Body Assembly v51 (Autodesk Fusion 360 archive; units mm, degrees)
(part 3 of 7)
circular_pattern "C-Pattern1" TotalAngle 360
align "Align1"
circular_pattern "C-Pattern1" TotalAngle 360
circular_pattern "C-Pattern2" TotalAngle 360
copy_paste_bodies "CopyPasteBodies1"
move "Move4"
align "Align7"
offset_faces "OffsetFaces3" distance 4
copy_paste_bodies "CopyPasteBodies2"
move "Move5"
align "Align8"
offset_faces "OffsetFaces6" distance 5
circular_pattern "C-Pattern1" TotalAngle 360
component_from_bodies "Body->Comp7"
copy_paste_bodies "CutPasteBodies1"
copy_paste_bodies "CutPasteBodies1"
copy_paste "CutPaste1"
extrude "Extrude5" add of existing geometry blind 1.5875 (= "( 1 / 16 ) * 1 in")
copy_paste_bodies "CopyPasteBodies3"
move "Move6"
align "Align9"
copy_paste_bodies "CopyPasteBodies4"
move "Move7"
align "Align10"
offset_faces "OffsetFaces4" distance 9
copy_paste_bodies "CutPasteBodies2"
component_from_bodies "Body->Comp8"
copy_paste "CutPaste2"
hole "Hole1" HoleDepth 93.98 HoleDiameter 3.5 (= "m3_diam") TipAngle 180
copy_paste_bodies "CopyPasteBodies5"
move "Move8"
align "Align11"
offset_faces "OffsetFaces5" distance 9
copy_paste_bodies "CopyPasteBodies6"
move "Move9"
align "Align12"
copy_paste_bodies "CopyPasteBodies7"
move "Move10"
align "Align13"
copy_paste_bodies "CopyPasteBodies8"
move "Move11"
align "Align14"
copy_paste_bodies "CutPasteBodies1"
copy_paste_bodies "CutPasteBodies2"
copy_paste_bodies "CutPasteBodies1"
copy_paste_bodies "CutPasteBodies2"
hole "Hole2" HoleDepth 93.98 HoleDiameter 3.5 (= "m3_diam") TipAngle 180
copy_paste_bodies "CopyPasteBodies9"
move "Move12"
copy_paste_bodies "CutPasteBodies1"
remove_instance "RemoveInstance1"
align "Align15"
copy_paste_bodies "CopyPasteBodies10"
move "Move13"
align "Align16"
offset_faces "OffsetFaces7" distance 4
copy_paste_bodies "CutPasteBodies3"
component_from_bodies "Body->Comp9"
copy_paste "CutPaste3"
sketch "Sketch18" plane through (0, 31.2082, 0) normal (0, 1, 0) x axis (-1, 0, 0)
  line L1 (19.3368, 119.7802) -> (48.8446, 86.3536)
  line L2 (-41.2985, 83.1939) -> (1.411, 120.8964)
  line L3 (-12.9069, 31.8415) -> (-42.4147, 65.2681)
  line L4 (47.7284, 68.4278) -> (5.0189, 30.7253)
  line L5 (47.7284, 68.4278) -> (1.411, 120.8964)
  line L6 (10.932, 129.3012) -> (57.2494, 76.8326)
  line L7 (57.2494, 76.8326) -> (47.7284, 68.4278)
  line L8 (1.411, 120.8964) -> (10.932, 129.3012)
  line L9 (-50.8195, 74.7891) -> (-4.5021, 22.3205)
  line L10 (-41.2985, 83.1939) -> (-50.8195, 74.7891)
  line L11 (-41.2985, 83.1939) -> (5.0189, 30.7253)
  line L12 (-4.5021, 22.3205) -> (5.0189, 30.7253)
  line L13 (6.1715, 125.0988) -> (52.4889, 72.6302)
  arc A1 centre (39.3236, 77.9488) radius 12.7 clockwise from (48.8446, 86.3536) to (47.7284, 68.4278)
  arc A2 centre (9.8158, 111.3754) radius 12.7 clockwise from (1.411, 120.8964) to (19.3368, 119.7802)
  arc A3 centre (-32.8937, 73.6729) radius 12.7 clockwise from (-42.4147, 65.2681) to (-41.2985, 83.1939)
  arc A4 centre (-3.3859, 40.2463) radius 12.7 clockwise from (5.0189, 30.7253) to (-12.9069, 31.8415)
  circle C1 centre (7.2492, 46.2916) radius 1.5
  circle C2 centre (14.5961, 52.7772) radius 1.5
  circle C3 centre (24.6588, 61.6601) radius 1.5
  circle C4 centre (32.0057, 68.1457) radius 1.5
  circle C5 centre (-0.8193, 105.3301) radius 1.5
  circle C6 centre (-8.1663, 98.8445) radius 1.5
  circle C7 centre (-18.2289, 89.9616) radius 1.5
  circle C8 centre (-25.5758, 83.476) radius 1.5
  point P38 (52.4889, 72.6302)
  point P39 (6.1715, 125.0988)
  point P40 (41.9374, 84.583)
  point P41 (16.723, 113.146)
  midpoint L7 P38
  midpoint L8 P39
  coincident L13 P40
  coincident L13 P41
  dimension "d480" distance P40 P41 = 38.1
  dimension "d481" distance L8 P41 = 15.9438 (= "( 2.7554133858267762 in - d480 ) / 2")
hole "Hole1" HoleDepth 93.98 HoleDiameter 3.5 (= "m3_diam") TipAngle 180
work_plane "WorkPlane9"
mirror "Mirror1" mirrorStitchTolerance 0.1016
copy_paste_bodies "CopyPasteBodies11"
move "Move14"
offset_faces "OffsetFaces8" distance -15
align "Align18"
copy_paste_bodies "CopyPasteBodies12"
move "Move15"
copy_paste_bodies "CopyPasteBodies13"
move "Move16"
copy_paste_bodies "CopyPasteBodies14"
move "Move17"
copy_paste_bodies "CopyPasteBodies15"
move "Move18"
align "Align19"
align "Align20"
align "Align21"
align "Align22"
component_from_bodies "Body->Comp10"
copy_paste "CutPaste4"
remove_body "RemoveBody36"
copy_paste_bodies "CutPasteBodies2"
mirror "Mirror2" mirrorStitchTolerance 0.1016
copy_paste "CutPaste5"
sketch "Sketch1" plane through (0, -40.4, 0) normal (0, -1, 0) x axis (1, 0, 0)
  line L1 (-22.1095, 68.8108) -> (-20.4063, 65.8608)
  line L2 (-20.4063, 71.7608) -> (-22.1095, 68.8108)
  line L3 (-16.9999, 71.7608) -> (-20.4063, 71.7608)
  line L4 (-15.2968, 68.8108) -> (-16.9999, 71.7608)
  line L5 (-16.9999, 65.8608) -> (-15.2968, 68.8108)
  line L6 (-20.4063, 65.8608) -> (-16.9999, 65.8608)
  line L7 (-11.7031, 72.4045) -> (-8.7531, 74.1077)
  line L8 (-14.6531, 74.1077) -> (-11.7031, 72.4045)
  line L9 (-14.6531, 77.514) -> (-14.6531, 74.1077)
  line L10 (-11.7031, 79.2172) -> (-14.6531, 77.514)
  line L11 (-8.7531, 77.514) -> (-11.7031, 79.2172)
  line L12 (-8.7531, 74.1077) -> (-8.7531, 77.514)
  line L13 (-15.2968, 82.8108) -> (-16.9999, 85.7608)
  line L14 (-16.9999, 79.8608) -> (-15.2968, 82.8108)
  line L15 (-20.4063, 79.8608) -> (-16.9999, 79.8608)
  line L16 (-22.1095, 82.8108) -> (-20.4063, 79.8608)
  line L17 (-20.4063, 85.7608) -> (-22.1095, 82.8108)
  line L18 (-16.9999, 85.7608) -> (-20.4063, 85.7608)
  line L19 (-25.7031, 79.2172) -> (-28.6531, 77.514)
  line L20 (-22.7531, 77.514) -> (-25.7031, 79.2172)
  line L21 (-22.7531, 74.1077) -> (-22.7531, 77.514)
  line L22 (-25.7031, 72.4045) -> (-22.7531, 74.1077)
  line L23 (-28.6531, 74.1077) -> (-25.7031, 72.4045)
  line L24 (-28.6531, 77.514) -> (-28.6531, 74.1077)
  line L25 (31.5525, 35.3457) -> (-37.9823, 35.3457)
  line L26 (-37.9823, 9.9457) -> (31.5525, 9.9457)
  line L27 (-37.9823, 60.7457) -> (-37.9823, 9.9457)
  line L28 (31.5525, 60.7457) -> (-37.9823, 60.7457)
  line L29 (31.5525, 9.9457) -> (31.5525, 60.7457)
  line L30 (-37.9823, 60.7457) -> (31.5525, 9.9457)
  line L31 (31.5525, 60.7457) -> (-37.9823, 9.9457)
  circle C1 centre (-50.4299, 36.1365) radius 1.75
  circle C2 centre (-18.7031, 75.8108) radius 1.75
  arc A1 centre (-18.7031, 75.8108) radius 12.4125 clockwise from (-24.9776, 86.5207) to (-12.1117, 65.293)
  arc A2 centre (12.7387, 22.1428) radius 74.6125 clockwise from (-60.1078, 38.2805) to (-24.9776, 86.5207)
  arc A3 centre (-50.4299, 36.1365) radius 9.9125 clockwise from (-41.43, 31.982) to (-60.1078, 38.2805)
  arc A4 centre (29.1955, -0.6206) radius 77.7875 clockwise from (-41.43, 31.982) to (-12.1117, 65.293)
  arc A5 centre (153.1884, 104.2222) radius 203.2 clockwise from (3.4186, -33.1067) to (-39.5235, 39.7834)
  arc A6 centre (-159.6183, 104.2222) radius 203.2 clockwise from (33.0936, 39.7834) to (-9.8485, -33.1067)
  arc A7 centre (-35.6254, -0.6206) radius 76.2 clockwise from (4.8389, 63.9479) to (33.5588, 31.3166)
  arc A8 centre (29.1955, -0.6206) radius 76.2 clockwise from (-39.9887, 31.3166) to (-11.2687, 63.9479)
  point P47 (31.5525, 35.3457)
  point P46 (-37.9823, 35.3457)
  point P52 (-3.2149, 35.3457)
  coincident A6 P47
  coincident A7 P47
  coincident A5 P46
  coincident A8 P46
  horizontal L26
  perpendicular L26 L27
  parallel L26 L28
  parallel L27 L29
  coincident L30 P52
  coincident L31 P52
  midpoint L25 P52
  coincident P47 L29
  dimension "d494" distance L26 L28 = 50.8
extrude "Extrude1" new body sketch "Sketch1" profile of A5 A6 A7 A8 L26 L28 against normal blind 19.05 and along normal blind 6.85
component_from_bodies "Body->Comp2"
as_built_joint "As-built1"
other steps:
base_feature "Base Feature1"
base_feature "Base Feature1"
base_feature "Base Feature1"
base_feature "Base Feature1"
base_feature "Base Feature1"
base_feature "Base Feature1"
base_feature "Base Feature1"
derived_base_feature "Derived Base Feature"
base_feature "Base Feature1"
base_feature "Base Feature3"
base_feature "Base Feature1"
base_feature "Base Feature2"
base_feature "Base Feature2"
base_feature "Base Feature3"
base_feature "Base Feature1"
base_feature "Base Feature1"
base_feature "Base Feature2"
base_feature "Base Feature3"
base_feature "Base Feature1"
base_feature "Base Feature2"
base_feature "Base Feature3"
base_feature "Base Feature1"
base_feature "Base Feature2"
base_feature "Base Feature2"
base_feature "Base Feature3"
base_feature "Base Feature4"
base_feature "Base Feature1"
base_feature "Base Feature1"
extrude "Extrude1" cut sketch "Sketch10" profile of L3 L4 L5 L6 A5 A6 A7 A8 L7 L8 L9 L10 L11 L12 L13 L14 distance -119.38
fillet "Fillet2" radius 1.5
base_feature "Base Feature1"
hole "Hole1" HoleDepth 93.98 HoleDiameter 3.5 (= "m3_diam") TipAngle 180
hole "Hole2" HoleDepth 93.98 HoleDiameter 3.5 (= "m3_diam") TipAngle 180
base_feature "Base Feature1"
delete_face "DeleteFace5"
delete_face "DeleteFace6"
delete_face "DeleteFace7"
base_feature "Base Feature1"
base_feature "Base Feature2"
base_feature "Base Feature3"
offset_faces "OffsetFaces1" distance -3.175
chamfer "Chamfer1" distance 4.7625
base_feature "Base Feature1"
chamfer "Chamfer1" distance 1.5875 (= "( 1 / 16 ) * 1 in")
hole "Hole4" HoleDepth 93.98 HoleDiameter 3.5 (= "m3_diam") TipAngle 180
hole "Hole5" HoleDepth 93.98 HoleDiameter 3.5 (= "m3_diam") TipAngle 180
base_feature "Base Feature1"
hole "Hole5" HoleDepth 93.98 HoleDiameter 3.5 (= "m3_diam") TipAngle 180
base_feature "Base Feature1"
base_feature "Base Feature1"
base_feature "Base Feature2"
base_feature "Base Feature3"
base_feature "Base Feature4"
base_feature "Base Feature5"
base_feature "Base Feature6"
base_feature "Base Feature7"
base_feature "Base Feature8"
base_feature "Base Feature9"
base_feature "Base Feature10"
base_feature "Base Feature11"
base_feature "Base Feature12"
base_feature "Base Feature13"
base_feature "Base Feature14"
base_feature "Base Feature15"
create_component "CreateComponent1"
create_component "CreateComponent2"
create_component "CreateComponent1"
create_component "CreateComponent1"
create_component "CreateComponent2"
create_component "CreateComponent2"
remove_body "RemoveBody1"
remove_body "RemoveBody1"
remove_body "RemoveBody2"
create_component "CreateComponent3"
remove_body "RemoveBody1"
create_component "CreateComponent3"
remove_body "RemoveBody3"
remove_instance "RemoveInstance1"
create_component "CreateComponent4"
remove_instance "RemoveInstance2"
remove_body "RemoveBody1"
remove_body "RemoveBody4"
create_component "CreateComponent1"
remove_body "RemoveBody2"
remove_body "RemoveBody3"
remove_body "RemoveBody4"
remove_body "RemoveBody6"
remove_instance "RemoveInstance1"
remove_body "RemoveBody7"
remove_body "RemoveBody9"
remove_instance "RemoveInstance1"
remove_body "RemoveBody5"
remove_body "RemoveBody6"
remove_body "RemoveBody1"
remove_body "RemoveBody2"
create_component "CreateComponent5"
remove_instance "RemoveInstance3"
create_component "CreateComponent1"
create_component "CreateComponent2"
create_component "CreateComponent3"
create_component "CreateComponent4"
create_component "CreateComponent5"
create_component "CreateComponent6"
create_component "CreateComponent6"
remove_instance "RemoveInstance1"
create_component "CreateComponent1"
remove_body "RemoveBody5"
create_component "CreateComponent2"
remove_body "RemoveBody6"
create_component "CreateComponent3"
remove_body "RemoveBody7"
create_component "CreateComponent7"
remove_instance "RemoveInstance5"
remove_instance "RemoveInstance2"
create_component "CreateComponent1"
create_component "CreateComponent26"
create_component "CreateComponent2"
create_component "CreateComponent3"
create_component "CreateComponent4"
remove_instance "RemoveInstance1"
remove_instance "RemoveInstance2"
remove_instance "RemoveInstance3"
create_component "CreateComponent7"
remove_body "RemoveBody1"
create_component "CreateComponent8"
remove_body "RemoveBody2"
create_component "CreateComponent9"
remove_body "RemoveBody3"
create_component "CreateComponent10"
remove_body "RemoveBody4"
remove_instance "RemoveInstance8"
remove_instance "RemoveInstance9"
remove_instance "RemoveInstance10"
remove_instance "RemoveInstance11"
remove_body "RemoveBody13"
create_component "CreateComponent1"
remove_body "RemoveBody1"
remove_instance "RemoveInstance14"
create_component "CreateComponent1"
create_component "CreateComponent2"
create_component "CreateComponent13"
create_component "CreateComponent14"
remove_body "RemoveBody14"
remove_body "RemoveBody15"
remove_body "RemoveBody16"
remove_body "RemoveBody17"
remove_body "RemoveBody18"
remove_body "RemoveBody19"
remove_body "RemoveBody20"
remove_body "RemoveBody21"
remove_instance "RemoveInstance15"
remove_body "RemoveBody22"
create_component "CreateComponent15"
remove_body "RemoveBody23"
remove_instance "RemoveInstance16"
remove_body "RemoveBody1"
remove_body "RemoveBody2"
remove_body "RemoveBody3"
remove_body "RemoveBody4"
remove_body "RemoveBody5"
remove_body "RemoveBody24"
remove_body "RemoveBody25"
remove_body "RemoveBody26"
remove_body "RemoveBody27"
remove_body "RemoveBody6"
remove_body "RemoveBody28"
create_component "CreateComponent16"
remove_body "RemoveBody29"
remove_instance "RemoveInstance17"
create_component "CreateComponent17"
remove_body "RemoveBody30"
remove_instance "RemoveInstance18"
remove_body "RemoveBody37"
remove_body "RemoveBody38"
remove_body "RemoveBody39"
remove_instance "RemoveInstance19"
create_component "CreateComponent2"
remove_body "RemoveBody2"

design "Electronics Box" references "USB host shield", "half proto board", "Teensy 4.1", "BTS790 Motor Driver"
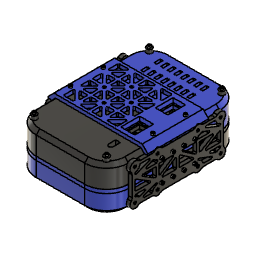
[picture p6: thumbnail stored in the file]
parameter "threadedinsertdiam" = 4.4
parameter "m3screwdiam" = 3.4
parameter "d454" = 6.4625 (= "0.1875 in + ( m3screwdiam / 2 )")
component_insert "Component Insert1"
component_insert "Component Insert2"
component_insert "Component Insert3"
position "Position2"
position "Position3"
component_insert "Component Insert4"
rectangular_pattern "Ё" uSpaceDistance 53 vSpaceDistance 0
rectangular_pattern "Ё" uSpaceDistance -53 vSpaceDistance 0
copy_paste "CutPaste1"
copy_paste "CutPaste2"
copy_paste "CutPaste3"
copy_paste "CutPaste4"
copy_paste "CutPaste5"
copy_paste "CutPaste6"
copy_paste "CutPaste7"
copy_paste "CutPaste8"
copy_paste "CutPaste1"
copy_paste "CutPaste2"
copy_paste "CutPaste3"
position "Position4"
position "Position5"
position "Position6"
position "Position7"
position "Position8"
sketch "Sketch1" plane through (0, 0, -1.65) normal (0, 0, -1) x axis (1, 0, 0)
  line L1 (-25, -25) -> (78, -25)
  line L2 (-25, 184) -> (-25, -25)
  line L3 (78, 184) -> (-25, 184)
  line L4 (78, -25) -> (78, 184)
  line L5 (-31.35, 190.35) -> (-31.35, -31.35)
  line L6 (84.35, 190.35) -> (-31.35, 190.35)
  line L7 (84.35, -31.35) -> (84.35, 190.35)
  line L8 (-31.35, -31.35) -> (84.35, -31.35)
  line L9 (-37.7, 196.7) -> (-37.7, -37.7)
  line L10 (90.7, 196.7) -> (-37.7, 196.7)
  line L11 (90.7, -37.7) -> (90.7, 196.7)
  line L12 (-37.7, -37.7) -> (90.7, -37.7)
  line L13 (90.7, -31.35) -> (84.35, -31.35)
  line L14 (90.7, 190.35) -> (84.35, 190.35)
  circle C1 centre (-20, 179) radius 1.5
  circle C2 centre (20, 179) radius 1.5
  circle C3 centre (20, 139) radius 1.5
  circle C4 centre (-20, 139) radius 1.5
  circle C5 centre (33, 179) radius 1.5
  circle C6 centre (73, 179) radius 1.5
  circle C7 centre (33, 139) radius 1.5
  circle C8 centre (73, 139) radius 1.5
  circle C9 centre (73, 126) radius 1.5
  circle C10 centre (33, 126) radius 1.5
  circle C11 centre (20, 126) radius 1.5
  circle C12 centre (-20, 126) radius 1.5
  circle C13 centre (-20, 86) radius 1.5
  circle C14 centre (20, 86) radius 1.5
  circle C15 centre (20, 73) radius 1.5
  circle C16 centre (20, 33) radius 1.5
  circle C17 centre (-20, 33) radius 1.5
  circle C18 centre (-20, 73) radius 1.5
  circle C19 centre (33, 73) radius 1.5
  circle C20 centre (73, 73) radius 1.5
  circle C21 centre (73, 33) radius 1.5
  circle C22 centre (33, 33) radius 1.5
  circle C23 centre (33, 20) radius 1.5
  circle C24 centre (73, 20) radius 1.5
  circle C25 centre (73, -20) radius 1.5
  circle C26 centre (33, -20) radius 1.5
  circle C27 centre (-20, -20) radius 1.5
  circle C28 centre (20, -20) radius 1.5
  circle C29 centre (20, 20) radius 1.5
  circle C30 centre (-20, 20) radius 1.5
  point P8 (73.5, -25)
  point P9 (78, -20.5)
  point P2 (-25, 179.5)
  point P3 (-20.5, 184)
  point P48 (90.7, -31.35)
  point P49 (90.7, 190.35)
  horizontal L1
  vertical L2
  horizontal L3
  vertical L4
  coincident L1 P8
  coincident L4 P9
  coincident P2 L2
  coincident P3 L3
  coincident L11 P48
  perpendicular L11 L13
  coincident L11 P49
  perpendicular L11 L14
  dimension "d11" = -6.35
  dimension "d12" = -12.7
extrude "Extrude1" new body sketch "Sketch1" profile of C1 C2 C3 C4 C5 C6 C7 C8 C9 C10 C11 C12 C13 C14 C15 C16 C17 C18 C19 C20 C21 C22 C23 C24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 along normal blind 6.35
extrude "Extrude2" add sketch "Sketch1" profile of L5 L6 L8 L11 L9 L10 L12 L13 L14 against normal blind 32
position "Position9"
sketch "Sketch2" plane through (0, 0, 30.35) normal (0, 0, 1) x axis (-1, 0, 0)
  line L1 (-90.7, -31.35) -> (31.35, -31.35)
  line L2 (-90.7, -37.7) -> (-90.7, -31.35)
  line L3 (37.7, -37.7) -> (-90.7, -37.7)
  line L4 (37.7, 196.7) -> (37.7, -37.7)
  line L5 (-90.7, 196.7) -> (37.7, 196.7)
  line L6 (-90.7, 190.35) -> (-90.7, 196.7)
  line L7 (31.35, 190.35) -> (-90.7, 190.35)
  line L8 (31.35, -31.35) -> (31.35, 190.35)
position "Position10"
sketch "Sketch3" plane through (0, 0, 30.35) normal (0, 0, 1) x axis (-1, 0, 0)
  line L1 (-90.7, -31.35) -> (31.35, -31.35)
  line L2 (-90.7, -37.7) -> (-90.7, -31.35)
  line L3 (37.7, -37.7) -> (-90.7, -37.7)
  line L4 (37.7, 196.7) -> (37.7, -37.7)
  line L5 (-90.7, 196.7) -> (37.7, 196.7)
  line L6 (-90.7, 190.35) -> (-90.7, 196.7)
  line L7 (31.35, 190.35) -> (-90.7, 190.35)
  line L8 (31.35, -31.35) -> (31.35, 190.35)
  line L9 (22.075, 30.875) -> (-54.725, 30.875)
  line L10 (-60.825, 141.175) -> (-60.825, 181.075)
  line L11 (14.175, 30.875) -> (31.35, 30.875)
  line L12 (14.175, 190.35) -> (14.175, 30.875)
  line L13 (31.35, 190.35) -> (14.175, 190.35)
  line L14 (31.35, 30.875) -> (31.35, 190.35)
  line L15 (-60.825, 30.875) -> (-46.825, 30.875)
  line L16 (-60.825, 190.35) -> (-60.825, 30.875)
  line L17 (-46.825, 190.35) -> (-60.825, 190.35)
  line L18 (-46.825, 30.875) -> (-46.825, 190.35)
  line L19 (-60.825, 30.875) -> (31.35, 30.875)
  line L20 (-60.825, 16.875) -> (-60.825, 30.875)
  line L21 (31.35, 16.875) -> (-60.825, 16.875)
  line L22 (31.35, 30.875) -> (31.35, 16.875)
  circle C1 centre (-53.175, 56.925) radius 1.5
  circle C2 centre (20.525, 56.925) radius 1.5
  point P9 (31.35, 190.35)
  point P17 (31.35, 190.35)
  point P11 (22.075, 30.875)
  point P8 (-90.7, 190.35)
  point P10 (-54.725, 30.875)
  point P13 (-60.825, 141.175)
  point P19 (-60.825, 30.875)
  point P23 (20.525, 56.925)
  point P22 (-53.175, 56.925)
  point P24 (-60.825, 30.875)
  point P25 (-60.825, 16.875)
  horizontal L11
  vertical L12
  horizontal L13
  vertical L14
  coincident P9 P17
  coincident P11 L11
  horizontal L15
  vertical L16
  horizontal L17
  vertical L18
  coincident P8 L17
  coincident P10 L15
  coincident P13 L16
  horizontal L19
  vertical L20
  horizontal L21
  vertical L22
  coincident P19 L20
  dimension "d15" distance L12 P23 = 6.35
  dimension "d16" distance L18 P22 = 6.35
  dimension "d19" distance P24 P25 = 14
extrude "Extrude3" add sketch "Sketch3" profile of L7 L8 L9 L10 L11 L12 L13 L14 L15 L16 L17 L18 C1 C2 L19 L20 L21 L22 against normal blind 6.35
component_insert "Component Insert5"
position "Position11"
component_insert "Component Insert6"
position "Position12"
position "Position13"
position "Position14"
position "Position15"
position "Position16"
position "Position17"
position "Position18"
position "Position19"
extrude "Extrude4" new body sketch "Sketch3" profile of L1 L2 L3 L4 L5 L6 L7 L8 L13 L14 L17 L22 along normal blind 25.4
sketch "Sketch4" plane through (0, 0, 55.75) normal (0, 0, 1) x axis (-1, 0, 0)
  line L1 (37.7, -37.7) -> (-90.7, -37.7)
  line L2 (37.7, 196.7) -> (37.7, -37.7)
  line L3 (-90.7, 196.7) -> (37.7, 196.7)
  line L4 (-90.7, -37.7) -> (-90.7, 196.7)
  point P3 (37.7, 196.7)
  point P6 (37.7, 196.7)
  point P2 (-90.7, -37.7)
  point P4 (-90.7, -37.7)
  horizontal L1
  vertical L2
  horizontal L3
  vertical L4
  coincident P3 P6
  coincident P2 P4
extrude "Extrude5" add sketch "Sketch4" along normal blind 6.35
sketch "Sketch5" plane through (-37.7, 0, 0) normal (-1, 0, 0) x axis (0, -1, 0)
  line L1 (115.3556, 46) -> (99.3556, 46)
  line L2 (115.3556, 53) -> (115.3556, 46)
  line L3 (99.3556, 53) -> (115.3556, 53)
  line L4 (99.3556, 46) -> (99.3556, 53)
  line L5 (121.7056, 39.65) -> (93.0056, 39.65)
  line L6 (121.7056, 59.35) -> (121.7056, 39.65)
  line L7 (93.0056, 59.35) -> (121.7056, 59.35)
  line L8 (93.0056, 39.65) -> (93.0056, 59.35)
  line L9 (93.0056, 59.35) -> (121.7056, 59.35)
  line L10 (93.0056, 68.4778) -> (93.0056, 59.35)
  line L11 (121.7056, 68.4778) -> (93.0056, 68.4778)
  line L12 (121.7056, 59.35) -> (121.7056, 68.4778)
  line L13 (163.2111, 46) -> (155.7111, 46)
  line L14 (163.2111, 49.07) -> (163.2111, 46)
  line L15 (155.7111, 49.07) -> (163.2111, 49.07)
  line L16 (155.7111, 46) -> (155.7111, 49.07)
  line L17 (169.5611, 39.65) -> (149.3611, 39.65)
  line L18 (169.5611, 55.42) -> (169.5611, 39.65)
  line L19 (149.3611, 55.42) -> (169.5611, 55.42)
  line L20 (149.3611, 39.65) -> (149.3611, 55.42)
  horizontal L9
  vertical L10
  horizontal L11
  vertical L12
  dimension "d24" = 6.35
  dimension "d25" = 6.35
copy_paste "CutPaste1"
copy_paste "CutPaste2"
copy_paste "CutPaste3"
copy_paste "CutPaste4"
extrude "Extrude6" cut sketch "Sketch5" profile of L13 L14 L15 L16 L17 L18 L19 L20 against normal blind 10.16
extrude "Extrude7" cut sketch "Sketch5" profile of L1 L2 L3 L4 L5 L6 L7 L8 L9 L10 L11 L12 against normal blind 25.4
sketch "Sketch6" plane through (0, 0, 62.1) normal (0, 0, 1) x axis (-1, 0, 0)
  line L1 (37.7, 121.7056) -> (12.3, 121.7056)
  line L2 (37.7, 196.7) -> (37.7, 121.7056)
  line L3 (-90.7, 196.7) -> (37.7, 196.7)
  line L4 (-90.7, -37.7) -> (-90.7, 196.7)
  line L5 (37.7, -37.7) -> (-90.7, -37.7)
  line L6 (37.7, 93.0056) -> (37.7, -37.7)
  line L7 (12.3, 93.0056) -> (37.7, 93.0056)
  line L8 (12.3, 121.7056) -> (12.3, 93.0056)
  line L9 (-60.825, 16.875) -> (31.35, 16.875)
  line L10 (-90.7, -31.35) -> (31.35, -31.35)
  line L11 (31.35, -31.35) -> (31.35, 190.35)
  line L12 (23.4125, -1.3625) -> (19.3525, -1.3625)
  line L13 (23.4125, 8.9375) -> (23.4125, -1.3625)
  line L14 (19.3525, 8.9375) -> (23.4125, 8.9375)
  line L15 (19.3525, -1.3625) -> (19.3525, 8.9375)
  line L16 (23.4125, 8.9375) -> (19.3525, -1.3625)
  line L17 (19.3525, 8.9375) -> (23.4125, -1.3625)
  line L18 (14.59, 13.7) -> (28.175, 13.7)
  line L19 (14.59, -6.125) -> (14.59, 13.7)
  line L20 (28.175, -6.125) -> (14.59, -6.125)
  line L21 (28.175, 13.7) -> (28.175, -6.125)
  line L22 (23.4125, -17.0625) -> (19.3525, -17.0625)
  line L23 (23.4125, -6.7625) -> (23.4125, -17.0625)
  line L24 (19.3525, -6.7625) -> (23.4125, -6.7625)
  line L25 (19.3525, -17.0625) -> (19.3525, -6.7625)
  line L26 (23.4125, -6.7625) -> (19.3525, -17.0625)
  line L27 (19.3525, -6.7625) -> (23.4125, -17.0625)
  line L28 (28.175, -2) -> (28.175, -21.825)
  line L29 (14.59, -2) -> (28.175, -2)
  line L30 (14.59, -21.825) -> (14.59, -2)
  line L31 (28.175, -21.825) -> (14.59, -21.825)
  point P20 (21.3825, 3.7875)
  point P29 (21.3825, -11.9125)
  point P16 (19.3525, -1.3625)
  point P17 (23.4125, -1.3625)
  point P19 (19.3525, 8.9375)
  point P25 (19.3525, -17.0625)
  point P26 (23.4125, -17.0625)
  point P28 (19.3525, -6.7625)
  horizontal L12
  perpendicular L12 L13
  parallel L12 L14
  parallel L13 L15
  coincident L16 P20
  coincident L17 P20
  horizontal L22
  perpendicular L22 L23
  parallel L22 L24
  parallel L23 L25
  coincident L26 P29
  coincident L27 P29
  dimension "d36" distance P16 P17 = 4.06
  dimension "d37" distance P16 P19 = 10.3
  dimension "d38" = 4.7625 (= "( 3 / 16 ) * 1 in")
  dimension "d39" distance L11 L21 = 3.175 (= "( 1 / 8 ) * 1 in")
  dimension "d40" distance L9 L18 = 3.175 (= "( 1 / 8 ) * 1 in")
  dimension "d47" distance P25 P26 = 4.06 (= "d36")
  dimension "d48" distance P25 P28 = 10.3 (= "d37")
  dimension "d49" = 4.7625 (= "( 3 / 16 ) * 1 in")
  dimension "d50" distance L11 L28 = 3.175 (= "d39")
  dimension "d51" distance L10 L31 = 9.525
sketch "Sketch7" plane through (0, 0, 62.1) normal (0, 0, 1) x axis (-1, 0, 0)
  line L1 (-74.31, 13.7) -> (28.175, 13.7)
  line L2 (-74.31, -21.825) -> (-74.31, 13.7)
  line L3 (28.175, -21.825) -> (-74.31, -21.825)
  line L4 (28.175, 13.7) -> (28.175, -21.825)
  point P2 (28.175, 13.7)
  point P3 (28.175, 13.7)
  horizontal L1
  vertical L2
  horizontal L3
  vertical L4
  coincident P2 P3
extrude "Extrude13" cut of existing geometry blind -0.3302
extrude "Extrude14" add of existing geometry blind 0.0002 (= "7.791E-06 in")
split "Split1"
split "Split2"
split "Split3"
combine "Combine2"
extrude "Extrude15" new body of existing geometry blind 25.4
extrude "Extrude16" new body of existing geometry blind 25.4
combine "Combine3"
combine "Combine4"
extrude "Extrude17" new body of existing geometry blind 6.35
extrude "Extrude18" add of existing geometry blind 223.52
extrude "Extrude19" new body of existing geometry blind 32.004
combine "Combine5"
combine "Combine6"
extrude "Extrude21" add of existing geometry blind 2.54
extrude "Extrude22" cut of existing geometry blind -27.94
position "Position20"
extrude "Extrude23" add of existing geometry blind 12.7
extrude "Extrude24" add of existing geometry blind 12.7
extrude "Extrude25" cut of existing geometry blind -12.7
split "Split4"
extrude "Extrude26" cut of existing geometry blind -12.7
move_face "MoveFace1"
fillet "Fillet2" radius 31.75
fillet "Fillet3" radius 38.1
chamfer "Chamfer3" distance 6.35
chamfer "Chamfer2" distance 2.6303
sketch "Sketch10" plane through (0, 0, 62.1) normal (0, 0, 1) x axis (-1, 0, 0)
  line L1 (-84.35, -31.35) -> (-0.4, -31.35)
  line L2 (-84.35, 14.65) -> (-84.35, -31.35)
  line L3 (-0.4, 14.65) -> (-84.35, 14.65)
  line L4 (-0.4, -31.35) -> (-0.4, 14.65)
  line L5 (-4.46, 14.65) -> (-0.4, 14.65)
  line L6 (-4.46, 4.35) -> (-4.46, 14.65)
  line L7 (-0.4, 4.35) -> (-4.46, 4.35)
  line L8 (-0.4, 14.65) -> (-0.4, 4.35)
  line L9 (-4.46, -8.35) -> (-0.4, -8.35)
  line L10 (-4.46, -18.65) -> (-4.46, -8.35)
  line L11 (-0.4, -18.65) -> (-4.46, -18.65)
  line L12 (-0.4, -8.35) -> (-0.4, -18.65)
  point P2 (-0.4, -31.35)
  point P4 (-0.4, -31.35)
  point P3 (-84.35, -31.35)
  point P5 (-84.35, -31.35)
  point P11 (-0.4, -8.35)
  point P9 (-4.46, 4.35)
  point P10 (-0.4, 4.35)
  point P8 (-4.46, 14.65)
  point P13 (-4.46, -18.65)
  point P14 (-0.4, -18.65)
  point P12 (-4.46, -8.35)
  horizontal L1
  vertical L2
  horizontal L3
  vertical L4
  coincident P2 P4
  coincident P3 P5
  horizontal L5
  vertical L6
  horizontal L7
  vertical L8
  horizontal L9
  vertical L10
  horizontal L11
  vertical L12
  coincident L4 P11
  dimension "d112" distance P9 P10 = 4.06
  dimension "d113" distance P8 P9 = 10.3
  dimension "d114" distance P13 P14 = 4.06 (= "d112")
  dimension "d115" distance P12 P13 = 10.3 (= "d113")
  dimension "d116" distance L1 L11 = 12.7
  dimension "d117" distance L7 L9 = 12.7
extrude "Extrude28" cut sketch "Sketch10" profile of L5 L6 L7 L8 L9 L10 L11 L12 against normal blind 27.94
rectangular_pattern "R-Pattern2" uSpaceDistance -79.89 (= "-3.3051181102362204 in + 4.06 mm") vSpaceDistance 0
sketch "Sketch11" plane through (0, 0, 55.75) normal (0, 0, -1) x axis (1, 0, 0)
  line L1 (84.35, 14.65) -> (80.29, 14.65)
  line L2 (84.35, 4.35) -> (84.35, 14.65)
  line L3 (80.29, 4.35) -> (84.35, 4.35)
  line L4 (80.29, 14.65) -> (80.29, 4.35)
  line L5 (84.35, -8.35) -> (80.29, -8.35)
  line L6 (84.35, -18.65) -> (84.35, -8.35)
  line L7 (80.29, -18.65) -> (84.35, -18.65)
  line L8 (80.29, -8.35) -> (80.29, -18.65)
  line L9 (72.9371, 14.65) -> (68.8771, 14.65)
  line L10 (72.9371, 4.35) -> (72.9371, 14.65)
  line L11 (68.8771, 4.35) -> (72.9371, 4.35)
  line L12 (68.8771, 14.65) -> (68.8771, 4.35)
  line L13 (72.9371, -8.35) -> (68.8771, -8.35)
  line L14 (72.9371, -18.65) -> (72.9371, -8.35)
  line L15 (68.8771, -18.65) -> (72.9371, -18.65)
  line L16 (68.8771, -8.35) -> (68.8771, -18.65)
  line L17 (61.5243, 14.65) -> (57.4643, 14.65)
  line L18 (61.5243, 4.35) -> (61.5243, 14.65)
  line L19 (57.4643, 4.35) -> (61.5243, 4.35)
  line L20 (57.4643, 14.65) -> (57.4643, 4.35)
  line L21 (61.5243, -8.35) -> (57.4643, -8.35)
  line L22 (61.5243, -18.65) -> (61.5243, -8.35)
  line L23 (57.4643, -18.65) -> (61.5243, -18.65)
  line L24 (57.4643, -8.35) -> (57.4643, -18.65)
  line L25 (50.1114, 14.65) -> (46.0514, 14.65)
  line L26 (50.1114, 4.35) -> (50.1114, 14.65)
  line L27 (46.0514, 4.35) -> (50.1114, 4.35)
  line L28 (46.0514, 14.65) -> (46.0514, 4.35)
  line L29 (50.1114, -8.35) -> (46.0514, -8.35)
  line L30 (50.1114, -18.65) -> (50.1114, -8.35)
  line L31 (46.0514, -18.65) -> (50.1114, -18.65)
  line L32 (46.0514, -8.35) -> (46.0514, -18.65)
  line L33 (38.6986, 14.65) -> (34.6386, 14.65)
  line L34 (38.6986, 4.35) -> (38.6986, 14.65)
  line L35 (34.6386, 4.35) -> (38.6986, 4.35)
  line L36 (34.6386, 14.65) -> (34.6386, 4.35)
  line L37 (38.6986, -8.35) -> (34.6386, -8.35)
  line L38 (38.6986, -18.65) -> (38.6986, -8.35)
  line L39 (34.6386, -18.65) -> (38.6986, -18.65)
  line L40 (34.6386, -8.35) -> (34.6386, -18.65)
  line L41 (27.2857, 14.65) -> (23.2257, 14.65)
  line L42 (27.2857, 4.35) -> (27.2857, 14.65)
  line L43 (23.2257, 4.35) -> (27.2857, 4.35)
  line L44 (23.2257, 14.65) -> (23.2257, 4.35)
  line L45 (27.2857, -8.35) -> (23.2257, -8.35)
  line L46 (27.2857, -18.65) -> (27.2857, -8.35)
  line L47 (23.2257, -18.65) -> (27.2857, -18.65)
  line L48 (23.2257, -8.35) -> (23.2257, -18.65)
  line L49 (15.8729, 14.65) -> (11.8129, 14.65)
  line L50 (15.8729, 4.35) -> (15.8729, 14.65)
  line L51 (11.8129, 4.35) -> (15.8729, 4.35)
  line L52 (11.8129, 14.65) -> (11.8129, 4.35)
  line L53 (15.8729, -8.35) -> (11.8129, -8.35)
  line L54 (15.8729, -18.65) -> (15.8729, -8.35)
  line L55 (11.8129, -18.65) -> (15.8729, -18.65)
  line L56 (11.8129, -8.35) -> (11.8129, -18.65)
  line L57 (4.46, 14.65) -> (0.4, 14.65)
  line L58 (4.46, 4.35) -> (4.46, 14.65)
  line L59 (0.4, 4.35) -> (4.46, 4.35)
  line L60 (0.4, 14.65) -> (0.4, 4.35)
  line L61 (4.46, -8.35) -> (0.4, -8.35)
  line L62 (4.46, -18.65) -> (4.46, -8.35)
  line L63 (0.4, -18.65) -> (4.46, -18.65)
  line L64 (0.4, -8.35) -> (0.4, -18.65)
  line L65 (90.7, 21) -> (-5.95, 21)
  line L66 (90.7, -34.525) -> (90.7, 21)
  line L67 (-5.95, -34.525) -> (90.7, -34.525)
  line L68 (-5.95, 21) -> (-5.95, -34.525)
  point P64 (4.46, -18.65)
  point P62 (0.4, -8.35)
  point P59 (4.46, 14.65)
  point P7 (84.35, -8.35)
  horizontal L65
  vertical L66
  horizontal L67
  vertical L68
  dimension "d124" distance P64 L67 = 15.875
  dimension "d125" distance P62 L68 = 6.35
  dimension "d126" distance P59 L65 = 6.35 (= "d125")
  dimension "d127" distance P7 L66 = 6.35 (= "d125")
extrude "Extrude29" add sketch "Sketch11" profile of L1 L2 L3 L4 L5 L6 L7 L8 L9 L10 L11 L12 L13 L14 L15 L16 L17 L18 L19 L20 L21 L22 L23 L24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 along normal blind 18
work_plane "WorkPlane2"
extrude "Extrude30" cut of existing geometry blind -0.8056
extrude "Extrude31" cut of existing geometry blind -0.8056
split "Split5"
extrude "Extrude34" new body of existing geometry blind 61.6204
extrude "Extrude35" new body of existing geometry blind 41.8846
combine "Combine7"
fillet "Fillet4" radius 38.1
split "Split6"
split "Split7"
remove_body "RemoveBody1"
remove_body "RemoveBody2"
position "Position21"
extrude "Extrude36" cut of existing geometry blind -12.7
extrude "Extrude37" add of existing geometry blind 12.7
split "Split8"
extrude "Extrude38" add of existing geometry blind 35.56
delete_face "DeleteFace1"
sketch "Sketch14" plane through (0, 0, 30.35) normal (0, 0, 1) x axis (-1, 0, 0)
  line L1 (-84.3454, -37.7096) -> (-0.4, -37.7096)
  line L2 (1.475, 79.5) -> (37.7, 79.5)
  line L3 (1.475, 18.175) -> (1.475, 79.5)
  line L4 (-59.525, 18.175) -> (1.475, 18.175)
  line L5 (-59.525, 79.5) -> (-59.525, 18.175)
  line L6 (-122.4454, 79.5) -> (-59.525, 79.5)
  line L7 (-122.4454, 0.3904) -> (-122.4454, 79.5)
  line L8 (-0.4, -37.7096) -> (-84.3454, -37.7096)
  line L9 (37.7, 79.5) -> (37.7, 0.3904)
  line L10 (37.7, 79.5) -> (1.475, 79.5)
  line L11 (37.7, 158.6) -> (37.7, 79.5)
  line L12 (-84.3454, 196.7) -> (-0.4, 196.7)
  line L13 (-122.4454, 79.5) -> (-122.4454, 158.6)
  line L14 (-59.525, 79.5) -> (-122.4454, 79.5)
  line L15 (-59.525, 177.65) -> (-59.525, 79.5)
  line L16 (1.475, 177.65) -> (-59.525, 177.65)
  line L17 (1.475, 79.5) -> (1.475, 177.65)
  line L18 (14.175, 92.2) -> (14.175, 179.4021)
  line L19 (25, 92.2) -> (14.175, 92.2)
  line L20 (25, 158.6) -> (25, 92.2)
  line L21 (-72.225, 184) -> (-72.225, 92.2)
  line L22 (-84.3454, 184) -> (-72.225, 184)
  line L23 (-109.7454, 92.2) -> (-109.7454, 158.6)
  line L24 (-72.225, 92.2) -> (-109.7454, 92.2)
  line L25 (-0.4, -25.0096) -> (-84.3454, -25.0096)
  line L26 (25, 66.8) -> (25, 0.3904)
  line L27 (14.175, 66.8) -> (25, 66.8)
  line L28 (14.175, 5.475) -> (14.175, 66.8)
  line L29 (-72.225, 5.475) -> (14.175, 5.475)
  line L30 (-72.225, 66.8) -> (-72.225, 5.475)
  line L31 (-109.7454, 66.8) -> (-72.225, 66.8)
  line L32 (-109.7454, 0.3904) -> (-109.7454, 66.8)
  line L33 (-109.7454, 92.2) -> (-109.7454, 66.8)
  line L34 (-72.225, 18.175) -> (14.175, 18.175)
  line L35 (-109.7454, 5.475) -> (-72.225, 5.475)
  line L36 (-73.525, 184) -> (-73.525, 5.475)
  line L37 (25, 18.175) -> (14.175, 18.175)
  line L38 (-73.525, 18.175) -> (-72.225, 18.175)
  arc A1 centre (-84.3454, 0.3904) radius 38.1 clockwise from (-84.3454, -37.7096) to (-122.4454, 0.3904)
  arc A2 centre (-0.4, 0.3904) radius 38.1 clockwise from (37.7, 0.3904) to (-0.4, -37.7096)
  arc A3 centre (-0.4, 158.6) radius 38.1 clockwise from (-0.4, 196.7) to (37.7, 158.6)
  arc A4 centre (-84.3454, 158.6) radius 38.1 clockwise from (-122.4454, 158.6) to (-84.3454, 196.7)
  arc A5 centre (-0.4, 158.6) radius 25.4 clockwise from (14.175, 179.4021) to (25, 158.6)
  arc A6 centre (-84.3454, 158.6) radius 25.4 clockwise from (-109.7454, 158.6) to (-84.3454, 184)
  arc A7 centre (-0.4, 0.3904) radius 25.4 clockwise from (25, 0.3904) to (-0.4, -25.0096)
  arc A8 centre (-84.3454, 0.3904) radius 25.4 clockwise from (-84.3454, -25.0096) to (-109.7454, 0.3904)
  point P51 (14.175, 18.175)
  point P52 (-72.225, 18.175)
  point P6 (1.475, 18.175)
  point P55 (-109.7454, 5.475)
  point P56 (-73.525, 5.475)
  point P53 (-73.525, 24.275)
  point P58 (25, 18.175)
  point P59 (-73.525, 18.175)
  coincident L28 P51
  coincident L30 P52
  perpendicular L30 L34
  coincident P6 L34
  coincident L32 P55
  perpendicular L32 L35
  coincident L35 P56
  perpendicular L35 L36
  coincident P53 L36
  coincident L26 P58
  perpendicular L26 L37
  coincident L36 P59
  perpendicular L36 L38
  dimension "d158" = -12.7
  dimension "d159" = -12.7
extrude "Extrude39" cut sketch "Sketch14" profile of L4 L6 L14 A6 L24 L22 L23 L31 L25 L28 A7 L26 L29 L30 L32 A8 L33 L34 L35 L36 L37 L38 against normal blind 20.32
extrude "Extrude40" add of existing geometry blind 3.175
extrude "Extrude41" add of existing geometry blind 43.18
sketch "Sketch15" plane through (0, -79.5, 0) normal (0, -1, 0) x axis (1, 0, 0)
  line L1 (122.45, 30.35) -> (116.1, 30.35)
  line L2 (122.45, 55.75) -> (122.45, 30.35)
  line L3 (116.1, 62.1) -> (122.45, 55.75)
  line L4 (-31.35, 62.1) -> (116.1, 62.1)
  line L5 (-37.7, 55.75) -> (-31.35, 62.1)
  line L6 (-37.7, 30.35) -> (-37.7, 55.75)
  line L7 (-31.35, 30.35) -> (-37.7, 30.35)
  line L8 (-31.35, 53.1197) -> (-31.35, 30.35)
  line L9 (-28.7197, 55.75) -> (-31.35, 53.1197)
  line L10 (113.4697, 55.75) -> (-28.7197, 55.75)
  line L11 (116.1, 53.1197) -> (113.4697, 55.75)
  line L12 (116.1, 30.35) -> (116.1, 53.1197)
  line L13 (116.1, 62.1) -> (-31.35, 62.1)
  line L14 (116.1, 62.1) -> (122.45, 55.75)
  line L15 (122.45, -8) -> (122.45, 55.75)
  point P17 (-31.35, 62.1)
  point P18 (-31.35, 62.1)
  point P16 (116.1, 62.1)
  point P19 (116.1, 62.1)
  point P15 (122.45, 55.75)
  point P20 (122.45, 55.75)
  point P14 (122.45, -8)
  point P21 (122.45, -8)
  coincident P17 P18
  coincident P16 P19
  coincident P15 P20
  coincident P14 P21
sketch "Sketch16" plane through (0, 0, -8) normal (0, 0, -1) x axis (1, 0, 0)
  line L1 (-37.7, 79.5) -> (122.45, 79.5)
  line L2 (-37.7, 0.4) -> (-37.7, 79.5)
  line L3 (84.35, -37.7) -> (0.4, -37.7)
  line L4 (122.45, 79.5) -> (122.45, 0.4)
  line L5 (128.8, 79.5) -> (122.45, 79.5)
  line L6 (128.8, 41.4) -> (128.8, 79.5)
  line L7 (122.45, 41.4) -> (128.8, 41.4)
  line L8 (122.45, 79.5) -> (122.45, 41.4)
  arc A1 centre (0.4, 0.4) radius 38.1 clockwise from (0.4, -37.7) to (-37.7, 0.4)
  arc A2 centre (84.35, 0.4) radius 38.1 clockwise from (122.45, 0.4) to (84.35, -37.7)
  point P2 (122.45, 79.5)
  point P11 (122.45, 79.5)
  point P13 (128.8, 41.4)
  point P14 (122.45, 41.4)
  point P12 (128.8, 79.5)
  horizontal L5
  vertical L6
  horizontal L7
  vertical L8
  coincident P2 P11
  dimension "d166" distance P13 P14 = 6.35
  dimension "d167" distance P12 P13 = 38.1
sweep "Sweep2" sketch "Sketch16" TwistAngle 0 TaperAngle 0
extrude "Extrude42" cut of existing geometry blind -139.7
sketch "Sketch17" plane through (128.8, 0, 0) normal (1, 0, 0) x axis (0, 1, 0)
  line L1 (-41.4, -8) -> (-79.5, -8)
  line L2 (-41.4, 58.3803) -> (-41.4, -8)
  line L3 (-79.5, 58.3803) -> (-41.4, 58.3803)
  line L4 (-79.5, -8) -> (-79.5, 58.3803)
  line L5 (-79.5, 24) -> (-79.5, -1.65)
  line L6 (-0.4, 24) -> (-79.5, 24)
  line L7 (-0.4, -1.65) -> (-0.4, 24)
  line L8 (-79.5, -1.65) -> (-0.4, -1.65)
  line L9 (-41.4, 58.3803) -> (-41.4, -8)
  line L10 (-79.5, 30.35) -> (-0.4, 30.35)
  line L11 (-79.5, 53.1197) -> (-79.5, 30.35)
  line L12 (-0.4, 53.1197) -> (-79.5, 53.1197)
  line L13 (-0.4, 30.35) -> (-0.4, 53.1197)
  line L14 (-41.4, 41.7349) -> (-79.5, 41.7349)
  line L15 (-41.4, 11.175) -> (-79.5, 11.175)
  point P16 (-79.5, 41.7349)
  point P17 (-41.4, 41.7349)
  point P18 (-79.5, 11.175)
  point P19 (-41.4, 11.175)
  point P20 (-69.975, 11.175)
  point P21 (-50.925, 11.175)
  point P22 (-50.925, 41.7349)
  point P23 (-69.975, 41.7349)
  midpoint L11 P16
  coincident L9 P17
  perpendicular L9 L14
  midpoint L5 P18
  coincident L9 P19
  perpendicular L9 L15
  coincident L15 P20
  coincident L15 P21
  coincident L14 P22
  coincident L14 P23
  dimension "d180" distance P18 P20 = 9.525
  dimension "d181" distance P19 P21 = 9.525 (= "d180")
  dimension "d182" distance P16 P23 = 9.525 (= "d180")
  dimension "d183" distance P17 P22 = 9.525 (= "d180")
hole "Hole1" HoleDepth 25.4 HoleDiameter 3.4 (= "m3screwdiam") TipAngle 180
sketch "Sketch18" plane through (122.45, 0, 0) normal (1, 0, 0) x axis (0, 1, 0)
  line L1 (-79.5, -8) -> (-79.5, 24)
  line L2 (-0.4, -8) -> (-79.5, -8)
  line L3 (-0.4, 24) -> (-0.4, -8)
  line L4 (-79.5, 24) -> (-0.4, 24)
hole "Hole2" HoleDepth 177.8 HoleDiameter 4.4 (= "threadedinsertdiam") TipAngle 180
mirror "Mirror3" mirrorStitchTolerance 0.1016
mirror "Mirror1" mirrorStitchTolerance 0.1016
work_plane "WorkPlane5"
mirror "Mirror2" mirrorStitchTolerance 0.1016
sketch "Sketch19" plane through (122.45, 0, 0) normal (1, 0, 0) x axis (0, 1, 0)
  line L1 (-79.5, 30.35) -> (-158.6, 30.35)
  line L2 (-158.6, 55.75) -> (-79.5, 55.75)
  line L3 (-158.6, 30.35) -> (-158.6, 55.75)
  line L4 (-41.4, -8) -> (-117.6, -8)
  line L5 (-41.4, 58.3803) -> (-41.4, -8)
  line L6 (-117.6, 58.3803) -> (-41.4, 58.3803)
  line L7 (-117.6, -8) -> (-117.6, 58.3803)
  circle C1 centre (-108.075, 11.175) radius 1.7
  circle C2 centre (-89.025, 41.7349) radius 1.7
  circle C3 centre (-108.075, 41.7349) radius 1.7
  circle C4 centre (-89.025, 11.175) radius 1.7
  circle C5 centre (-69.975, 11.175) radius 1.7
  circle C6 centre (-50.925, 41.7349) radius 1.7
  circle C7 centre (-69.975, 41.7349) radius 1.7
  circle C8 centre (-50.925, 11.175) radius 1.7
hole "Hole3" HoleDepth 190.5 HoleDiameter 4.4 (= "threadedinsertdiam") TipAngle 180
sketch "Sketch20" plane through (0, 0, -1.65) normal (0, 0, 1) x axis (-1, 0, 0)
  line L1 (-116.1, 0.4) -> (-116.1, 79.5)
  line L2 (31.35, 79.5) -> (31.35, 0.4)
  line L3 (-106.8006, -22.0506) -> (-84.35, 0.4)
  line L4 (-124.8544, -28.0129) -> (-111.2908, -14.4492)
  line L5 (-99.1992, -26.5408) -> (-112.7629, -40.1044)
  line L6 (-118.8086, -34.0586) -> (-105.245, -20.495)
  line L7 (-83.1465, 51.2) -> (-116.1, 51.2)
  line L8 (-136.6984, 59.75) -> (-113.9, 59.75)
  line L9 (-113.9, 42.65) -> (-136.6984, 42.65)
  line L10 (-136.6984, 51.2) -> (-113.9, 51.2)
  line L11 (-122.45, 0.4) -> (-122.45, 79.5)
  arc A1 centre (-84.35, 0.4) radius 31.75 clockwise from (-84.35, -31.35) to (-116.1, 0.4)
  arc A2 centre (-0.4, 0.4) radius 31.75 clockwise from (31.35, 0.4) to (-0.4, -31.35)
  circle C1 centre (-105.245, -20.495) radius 2.2
  circle C2 centre (-105.245, -20.495) radius 8.55
  arc A3 centre (-118.8086, -34.0586) radius 8.55 clockwise from (-112.7629, -40.1044) to (-124.8544, -28.0129)
  arc A4 centre (-105.245, -20.495) radius 8.55 clockwise from (-111.2908, -14.4492) to (-99.1992, -26.5408)
  arc A5 centre (-84.35, 0.4) radius 38.1 clockwise from (-84.35, -37.7) to (-122.45, 0.4)
  circle C3 centre (-113.9, 51.2) radius 2.2
  circle C4 centre (-113.9, 51.2) radius 8.55
  arc A6 centre (-136.6984, 51.2) radius 8.55 clockwise from (-136.6984, 42.65) to (-136.6984, 59.75)
  arc A7 centre (-113.9, 51.2) radius 8.55 clockwise from (-113.9, 59.75) to (-113.9, 42.65)
  point P4 (-84.35, 0.4)
  point P12 (-84.35, 0.4)
  point P13 (-106.8006, -22.0506)
  point P10 (-105.245, -20.495)
  point P18 (-105.245, -20.495)
  point P23 (-116.1, 51.2)
  point P25 (-116.1, 51.2)
  point P24 (-113.9, 51.2)
  point P32 (-113.9, 51.2)
  point P2 (-116.1, 0.4)
  coincident P4 P12
  midpoint A1 P13
  coincident P10 L3
  tangent L4 A3
  tangent A3 L5
  parallel L4 L5
  tangent L5 A4
  tangent L4 A4
  coincident P10 P18
  collinear L3 L6
  tangent C2 A4
  coincident L1 P23
  coincident P23 P25
  perpendicular L1 L7
  coincident P24 L7
  tangent L8 A6
  tangent A6 L9
  parallel L8 L9
  tangent L9 A7
  tangent L8 A7
  perpendicular L1 L10
  coincident P24 P32
  tangent C4 A7
  tangent A1 C1
  tangent L1 C3
  dimension "d197" diameter C1 = 4.4 (= "threadedinsertdiam")
  dimension "d198" = 6.35
  dimension "d199" distance P2 P23 = 50.8
  dimension "d200" diameter C3 = 4.4 (= "threadedinsertdiam")
  dimension "d201" = 6.35
extrude "Extrude43" new body sketch "Sketch20" profile of A1 L1 C1 L4 L5 A4 C3 L8 L9 A7 along normal blind 25.65
sketch "Sketch21" plane through (0, 0, 24) normal (0, 0, 1) x axis (-1, 0, 0)
  line L1 (-116.1, 59.75) -> (-113.9, 59.75)
  line L2 (-116.1, 42.65) -> (-116.1, 59.75)
  line L3 (-113.9, 42.65) -> (-116.1, 42.65)
  arc A1 centre (-113.9, 51.2) radius 8.55 clockwise from (-113.9, 59.75) to (-113.9, 42.65)
hole "Hole4" HoleDepth 10 HoleDiameter 4.4 (= "threadedinsertdiam") TipAngle 180
mirror "Mirror4" mirrorStitchTolerance 0.1016
mirror "Mirror5" mirrorStitchTolerance 0.1016
extrude "Extrude46" new body of existing geometry blind 15.24
extrude "Extrude47" new body of existing geometry blind 12.7
combine "Combine8"
combine "Combine9"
